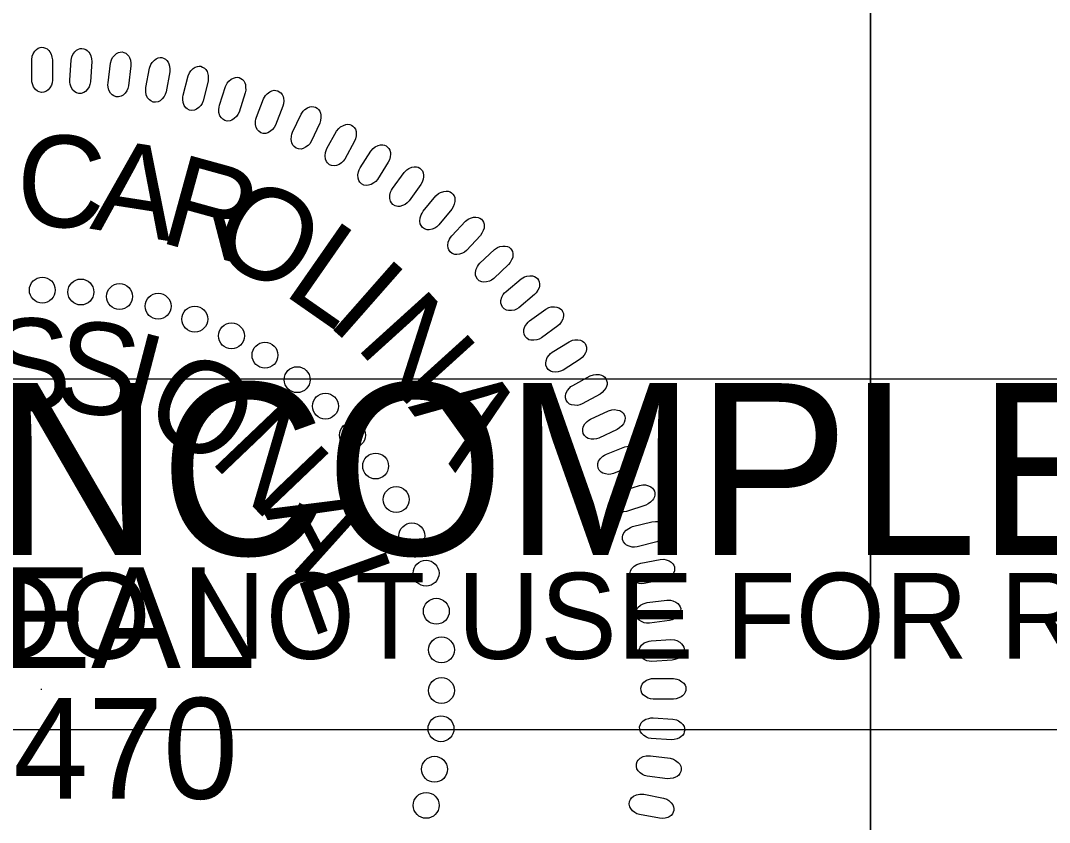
# Model space of a CAD drawing. Extents: x 18938 to 19565, y 6931 to 7973.
# Drawn here: x 19359.81 to 19368.08, y 7502.55 to 7509 of the extents above; entities that cross this region are included whole.
import ezdxf

# ---------------------------------------------------------------- set-up
doc = ezdxf.new("R2010")
doc.units = 0
for name, color, linetype in [('Old_Level_10', 7, 'Continuous'), ('Prop Pavement Schedule Description CELL', 7, 'Continuous'), ('Scratch_Level_5', 7, 'Continuous'), ('Typical Pavement Slope Information CELL', 7, 'Continuous')]:
    doc.layers.add(name, color=color, linetype=linetype)

# ---------------------------------------------------------------- blocks, each defined once
blk = doc.blocks.new('Brandon J. McInnis')
at = {"layer": 'Old_Level_10'}
blk.add_line((-51.239, 50.97), (-51.239, 50.923), dxfattribs=at)
for points in [[(-51.831, 88.656), (-51.831, 89.882), (-51.793, 90.102), (-51.74, 90.242), (-51.628, 90.411), (-51.531, 90.521), (-51.419, 90.601), (-51.315, 90.64), (-51.202, 90.66), (-51.09, 90.64), (-50.97, 90.61), (-50.866, 90.551), (-50.761, 90.451), (-50.701, 90.37), (-50.634, 90.221), (-50.574, 90.042), (-50.552, 89.882), (-50.545, 88.626), (-50.567, 88.456), (-50.613, 88.316), (-50.702, 88.157), (-50.815, 88.017), (-50.912, 87.938), (-51.069, 87.878), (-51.218, 87.858), (-51.367, 87.898), (-51.472, 87.947), (-51.6, 88.047), (-51.719, 88.217), (-51.786, 88.397), (-51.816, 88.526)], [(-49.472, 88.629), (-49.394, 89.854), (-49.344, 90.07), (-49.282, 90.206), (-49.159, 90.368), (-49.056, 90.472), (-48.939, 90.544), (-48.832, 90.577), (-48.718, 90.59), (-48.608, 90.563), (-48.49, 90.526), (-48.39, 90.46), (-48.291, 90.354), (-48.237, 90.27), (-48.179, 90.117), (-48.131, 89.934), (-48.118, 89.773), (-48.191, 88.518), (-48.223, 88.35), (-48.277, 88.214), (-48.377, 88.061), (-48.497, 87.928), (-48.599, 87.854), (-48.76, 87.805), (-48.911, 87.794), (-49.057, 87.843), (-49.158, 87.9), (-49.279, 88.008), (-49.387, 88.184), (-49.443, 88.368), (-49.465, 88.499)], [(-47.109, 88.454), (-46.955, 89.671), (-46.891, 89.884), (-46.821, 90.016), (-46.689, 90.17), (-46.578, 90.267), (-46.457, 90.332), (-46.348, 90.359), (-46.235, 90.364), (-46.126, 90.33), (-46.011, 90.285), (-45.915, 90.213), (-45.823, 90.101), (-45.774, 90.014), (-45.726, 89.857), (-45.69, 89.671), (-45.687, 89.511), (-45.838, 88.263), (-45.881, 88.097), (-45.943, 87.965), (-46.052, 87.818), (-46.181, 87.693), (-46.287, 87.626), (-46.451, 87.587), (-46.601, 87.585), (-46.745, 87.644), (-46.842, 87.706), (-46.956, 87.821), (-47.054, 88.005), (-47.097, 88.191), (-47.111, 88.324)], [(-44.77, 88.168), (-44.54, 89.372), (-44.462, 89.581), (-44.384, 89.708), (-44.242, 89.854), (-44.126, 89.943), (-44.001, 90), (-43.891, 90.02), (-43.777, 90.019), (-43.671, 89.978), (-43.559, 89.926), (-43.467, 89.848), (-43.383, 89.73), (-43.339, 89.641), (-43.301, 89.481), (-43.276, 89.294), (-43.284, 89.132), (-43.513, 87.897), (-43.567, 87.735), (-43.637, 87.606), (-43.755, 87.466), (-43.891, 87.35), (-44.002, 87.29), (-44.167, 87.26), (-44.318, 87.269), (-44.457, 87.336), (-44.55, 87.405), (-44.656, 87.527), (-44.742, 87.716), (-44.775, 87.904), (-44.779, 88.038)], [(-42.465, 87.694), (-42.159, 88.882), (-42.069, 89.085), (-41.983, 89.208), (-41.832, 89.344), (-41.711, 89.426), (-41.582, 89.475), (-41.471, 89.488), (-41.357, 89.479), (-41.254, 89.432), (-41.145, 89.373), (-41.059, 89.289), (-40.983, 89.167), (-40.945, 89.075), (-40.917, 88.913), (-40.903, 88.724), (-40.921, 88.563), (-41.227, 87.345), (-41.291, 87.187), (-41.37, 87.062), (-41.496, 86.93), (-41.639, 86.823), (-41.753, 86.769), (-41.92, 86.751), (-42.07, 86.769), (-42.204, 86.845), (-42.293, 86.919), (-42.392, 87.047), (-42.466, 87.241), (-42.486, 87.432), (-42.483, 87.564)], [(-40.215, 87.072), (-39.835, 88.239), (-39.732, 88.436), (-39.639, 88.552), (-39.48, 88.679), (-39.353, 88.753), (-39.222, 88.794), (-39.11, 88.8), (-38.997, 88.784), (-38.897, 88.73), (-38.793, 88.664), (-38.711, 88.575), (-38.643, 88.449), (-38.611, 88.354), (-38.593, 88.191), (-38.592, 88.002), (-38.619, 87.843), (-39.001, 86.646), (-39.075, 86.491), (-39.161, 86.372), (-39.295, 86.248), (-39.446, 86.151), (-39.562, 86.105), (-39.73, 86.096), (-39.879, 86.124), (-40.008, 86.208), (-40.092, 86.288), (-40.183, 86.422), (-40.244, 86.62), (-40.252, 86.811), (-40.24, 86.944)], [(-37.931, 86.337), (-37.48, 87.477), (-37.364, 87.667), (-37.264, 87.778), (-37.097, 87.895), (-36.966, 87.961), (-36.833, 87.993), (-36.721, 87.992), (-36.609, 87.97), (-36.513, 87.91), (-36.412, 87.838), (-36.337, 87.743), (-36.276, 87.612), (-36.25, 87.516), (-36.242, 87.352), (-36.253, 87.163), (-36.291, 87.007), (-36.747, 85.835), (-36.831, 85.686), (-36.924, 85.573), (-37.066, 85.458), (-37.221, 85.369), (-37.341, 85.331), (-37.509, 85.333), (-37.656, 85.37), (-37.78, 85.462), (-37.859, 85.547), (-37.94, 85.686), (-37.988, 85.888), (-37.985, 86.08), (-37.965, 86.211)], [(-35.69, 85.403), (-35.167, 86.513), (-35.04, 86.695), (-34.933, 86.799), (-34.76, 86.905), (-34.625, 86.963), (-34.49, 86.987), (-34.378, 86.979), (-34.268, 86.949), (-34.175, 86.883), (-34.079, 86.805), (-34.01, 86.706), (-33.958, 86.571), (-33.938, 86.474), (-33.941, 86.309), (-33.963, 86.122), (-34.011, 85.968), (-34.54, 84.828), (-34.632, 84.684), (-34.733, 84.577), (-34.882, 84.471), (-35.043, 84.392), (-35.165, 84.361), (-35.332, 84.374), (-35.476, 84.42), (-35.593, 84.52), (-35.667, 84.609), (-35.74, 84.754), (-35.775, 84.958), (-35.76, 85.149), (-35.732, 85.279)], [(-33.566, 84.388), (-32.975, 85.462), (-32.836, 85.636), (-32.723, 85.734), (-32.543, 85.828), (-32.405, 85.877), (-32.268, 85.893), (-32.158, 85.878), (-32.05, 85.841), (-31.961, 85.77), (-31.871, 85.686), (-31.808, 85.583), (-31.764, 85.445), (-31.75, 85.346), (-31.763, 85.183), (-31.798, 84.997), (-31.854, 84.846), (-32.454, 83.742), (-32.555, 83.604), (-32.662, 83.503), (-32.817, 83.407), (-32.983, 83.338), (-33.107, 83.315), (-33.273, 83.338), (-33.414, 83.393), (-33.526, 83.5), (-33.593, 83.594), (-33.656, 83.743), (-33.679, 83.949), (-33.652, 84.139), (-33.616, 84.267)], [(-31.508, 83.203), (-30.85, 84.238), (-30.701, 84.403), (-30.582, 84.493), (-30.397, 84.576), (-30.256, 84.617), (-30.118, 84.624), (-30.009, 84.602), (-29.903, 84.558), (-29.819, 84.481), (-29.735, 84.392), (-29.678, 84.285), (-29.643, 84.145), (-29.636, 84.046), (-29.659, 83.883), (-29.705, 83.699), (-29.771, 83.553), (-30.439, 82.488), (-30.549, 82.357), (-30.661, 82.264), (-30.823, 82.177), (-30.992, 82.119), (-31.117, 82.103), (-31.282, 82.137), (-31.418, 82.201), (-31.523, 82.314), (-31.585, 82.413), (-31.639, 82.565), (-31.649, 82.772), (-31.609, 82.96), (-31.565, 83.085)], [(-29.508, 81.929), (-28.787, 82.921), (-28.628, 83.078), (-28.503, 83.16), (-28.313, 83.231), (-28.17, 83.262), (-28.032, 83.261), (-27.924, 83.231), (-27.821, 83.182), (-27.742, 83.1), (-27.664, 83.005), (-27.614, 82.896), (-27.588, 82.753), (-27.586, 82.653), (-27.62, 82.493), (-27.677, 82.313), (-27.753, 82.17), (-28.486, 81.149), (-28.604, 81.026), (-28.722, 80.939), (-28.888, 80.862), (-29.061, 80.815), (-29.187, 80.808), (-29.349, 80.852), (-29.481, 80.924), (-29.579, 81.044), (-29.634, 81.146), (-29.679, 81.301), (-29.675, 81.509), (-29.624, 81.694), (-29.572, 81.816)], [(-27.614, 80.513), (-26.831, 81.458), (-26.663, 81.603), (-26.534, 81.678), (-26.339, 81.737), (-26.194, 81.76), (-26.057, 81.749), (-25.951, 81.713), (-25.852, 81.657), (-25.778, 81.571), (-25.705, 81.471), (-25.663, 81.358), (-25.646, 81.215), (-25.65, 81.115), (-25.695, 80.957), (-25.762, 80.78), (-25.846, 80.643), (-26.642, 79.671), (-26.768, 79.554), (-26.892, 79.475), (-27.062, 79.41), (-27.238, 79.373), (-27.364, 79.373), (-27.523, 79.428), (-27.65, 79.508), (-27.74, 79.634), (-27.789, 79.739), (-27.823, 79.897), (-27.807, 80.103), (-27.744, 80.285), (-27.684, 80.404)], [(-25.842, 78.999), (-25.002, 79.893), (-24.825, 80.028), (-24.691, 80.094), (-24.493, 80.14), (-24.347, 80.154), (-24.211, 80.135), (-24.107, 80.093), (-24.011, 80.03), (-23.944, 79.939), (-23.877, 79.835), (-23.841, 79.72), (-23.834, 79.576), (-23.845, 79.476), (-23.898, 79.321), (-23.977, 79.15), (-24.07, 79.018), (-24.926, 78.097), (-25.058, 77.989), (-25.186, 77.918), (-25.361, 77.864), (-25.538, 77.838), (-25.664, 77.847), (-25.819, 77.91), (-25.942, 77.998), (-26.023, 78.13), (-26.065, 78.238), (-26.09, 78.397), (-26.061, 78.603), (-25.987, 78.779), (-25.92, 78.894)], [(-24.098, 77.306), (-23.203, 78.145), (-23.018, 78.268), (-22.88, 78.326), (-22.68, 78.36), (-22.533, 78.364), (-22.399, 78.337), (-22.297, 78.288), (-22.206, 78.22), (-22.144, 78.124), (-22.084, 78.017), (-22.056, 77.899), (-22.057, 77.755), (-22.075, 77.657), (-22.138, 77.505), (-22.227, 77.339), (-22.328, 77.213), (-23.24, 76.348), (-23.379, 76.248), (-23.511, 76.185), (-23.689, 76.142), (-23.867, 76.128), (-23.992, 76.144), (-24.143, 76.218), (-24.26, 76.313), (-24.334, 76.449), (-24.369, 76.56), (-24.383, 76.721), (-24.341, 76.924), (-24.256, 77.096), (-24.182, 77.206)], [(-22.486, 75.559), (-21.54, 76.341), (-21.347, 76.452), (-21.206, 76.501), (-21.004, 76.522), (-20.857, 76.517), (-20.725, 76.482), (-20.627, 76.426), (-20.54, 76.353), (-20.484, 76.254), (-20.431, 76.142), (-20.41, 76.023), (-20.421, 75.879), (-20.444, 75.782), (-20.517, 75.635), (-20.617, 75.475), (-20.726, 75.356), (-21.69, 74.55), (-21.834, 74.459), (-21.971, 74.404), (-22.151, 74.372), (-22.33, 74.369), (-22.453, 74.393), (-22.6, 74.476), (-22.71, 74.579), (-22.774, 74.719), (-22.803, 74.832), (-22.807, 74.993), (-22.752, 75.193), (-22.657, 75.36), (-22.576, 75.465)], [(-21.026, 73.737), (-20.033, 74.458), (-19.833, 74.556), (-19.69, 74.596), (-19.486, 74.605), (-19.341, 74.591), (-19.21, 74.547), (-19.116, 74.486), (-19.034, 74.407), (-18.984, 74.304), (-18.939, 74.19), (-18.925, 74.07), (-18.945, 73.927), (-18.974, 73.831), (-19.056, 73.689), (-19.166, 73.535), (-19.281, 73.423), (-20.294, 72.679), (-20.444, 72.598), (-20.584, 72.552), (-20.765, 72.531), (-20.945, 72.54), (-21.066, 72.571), (-21.207, 72.663), (-21.311, 72.772), (-21.366, 72.917), (-21.387, 73.03), (-21.382, 73.192), (-21.315, 73.388), (-21.209, 73.548), (-21.121, 73.649)], [(-19.625, 71.791), (-18.589, 72.448), (-18.383, 72.534), (-18.238, 72.565), (-18.035, 72.561), (-17.889, 72.538), (-17.762, 72.486), (-17.672, 72.418), (-17.596, 72.335), (-17.552, 72.229), (-17.514, 72.112), (-17.508, 71.992), (-17.537, 71.85), (-17.572, 71.757), (-17.662, 71.619), (-17.782, 71.473), (-17.904, 71.369), (-18.961, 70.689), (-19.116, 70.618), (-19.259, 70.581), (-19.441, 70.571), (-19.619, 70.591), (-19.739, 70.63), (-19.874, 70.731), (-19.97, 70.846), (-20.017, 70.994), (-20.031, 71.109), (-20.014, 71.27), (-19.936, 71.461), (-19.82, 71.615), (-19.726, 71.709)], [(-18.364, 69.741), (-17.289, 70.332), (-17.078, 70.404), (-16.931, 70.426), (-16.728, 70.41), (-16.585, 70.377), (-16.461, 70.317), (-16.376, 70.244), (-16.305, 70.156), (-16.268, 70.048), (-16.237, 69.929), (-16.238, 69.809), (-16.276, 69.669), (-16.317, 69.578), (-16.416, 69.447), (-16.544, 69.308), (-16.673, 69.211), (-17.771, 68.6), (-17.931, 68.538), (-18.075, 68.51), (-18.257, 68.512), (-18.433, 68.543), (-18.551, 68.589), (-18.679, 68.698), (-18.768, 68.82), (-18.805, 68.97), (-18.812, 69.086), (-18.786, 69.245), (-18.694, 69.432), (-18.569, 69.577), (-18.47, 69.666)], [(-17.256, 67.658), (-16.146, 68.18), (-15.932, 68.239), (-15.784, 68.252), (-15.582, 68.222), (-15.442, 68.181), (-15.321, 68.113), (-15.241, 68.036), (-15.175, 67.943), (-15.146, 67.833), (-15.122, 67.712), (-15.131, 67.592), (-15.177, 67.455), (-15.224, 67.367), (-15.331, 67.241), (-15.468, 67.112), (-15.603, 67.023), (-16.737, 66.482), (-16.9, 66.431), (-17.045, 66.411), (-17.227, 66.425), (-17.402, 66.467), (-17.515, 66.52), (-17.636, 66.637), (-17.718, 66.764), (-17.745, 66.916), (-17.744, 67.032), (-17.709, 67.19), (-17.606, 67.37), (-17.472, 67.508), (-17.367, 67.589)], [(-16.277, 65.497), (-15.136, 65.948), (-14.919, 65.994), (-14.77, 65.997), (-14.571, 65.955), (-14.433, 65.905), (-14.318, 65.83), (-14.242, 65.747), (-14.182, 65.65), (-14.16, 65.538), (-14.143, 65.416), (-14.16, 65.298), (-14.215, 65.163), (-14.267, 65.078), (-14.381, 64.96), (-14.526, 64.839), (-14.666, 64.76), (-15.832, 64.29), (-15.998, 64.249), (-16.144, 64.239), (-16.326, 64.264), (-16.496, 64.317), (-16.607, 64.378), (-16.72, 64.502), (-16.793, 64.634), (-16.811, 64.787), (-16.803, 64.903), (-16.758, 65.058), (-16.644, 65.231), (-16.502, 65.36), (-16.392, 65.435)], [(-15.403, 63.183), (-14.236, 63.561), (-14.016, 63.593), (-13.867, 63.587), (-13.671, 63.533), (-13.536, 63.474), (-13.426, 63.392), (-13.356, 63.305), (-13.302, 63.204), (-13.287, 63.092), (-13.278, 62.969), (-13.303, 62.851), (-13.366, 62.72), (-13.422, 62.639), (-13.545, 62.528), (-13.696, 62.416), (-13.841, 62.345), (-15.034, 61.95), (-15.202, 61.92), (-15.349, 61.92), (-15.528, 61.955), (-15.696, 62.018), (-15.802, 62.087), (-15.908, 62.217), (-15.972, 62.353), (-15.98, 62.508), (-15.965, 62.623), (-15.91, 62.775), (-15.786, 62.94), (-15.636, 63.06), (-15.522, 63.129)], [(-14.658, 61.01), (-13.47, 61.314), (-13.249, 61.332), (-13.1, 61.317), (-12.907, 61.25), (-12.777, 61.184), (-12.672, 61.094), (-12.608, 61.003), (-12.56, 60.899), (-12.552, 60.786), (-12.551, 60.662), (-12.583, 60.547), (-12.654, 60.42), (-12.716, 60.342), (-12.844, 60.24), (-13.004, 60.137), (-13.152, 60.076), (-14.368, 59.757), (-14.537, 59.737), (-14.684, 59.745), (-14.861, 59.792), (-15.024, 59.866), (-15.125, 59.941), (-15.222, 60.078), (-15.279, 60.218), (-15.277, 60.372), (-15.255, 60.486), (-15.19, 60.634), (-15.056, 60.792), (-14.898, 60.902), (-14.78, 60.963)], [(-14.148, 58.755), (-12.944, 58.985), (-12.721, 58.989), (-12.574, 58.964), (-12.386, 58.885), (-12.261, 58.811), (-12.16, 58.715), (-12.102, 58.62), (-12.062, 58.514), (-12.061, 58.4), (-12.068, 58.276), (-12.107, 58.163), (-12.185, 58.041), (-12.252, 57.967), (-12.387, 57.873), (-12.552, 57.781), (-12.704, 57.729), (-13.938, 57.487), (-14.108, 57.477), (-14.253, 57.495), (-14.427, 57.554), (-14.585, 57.638), (-14.682, 57.718), (-14.77, 57.861), (-14.817, 58.005), (-14.806, 58.158), (-14.777, 58.27), (-14.703, 58.414), (-14.559, 58.563), (-14.394, 58.663), (-14.273, 58.716)], [(-13.75, 56.316), (-12.533, 56.469), (-12.311, 56.46), (-12.166, 56.426), (-11.983, 56.335), (-11.862, 56.253), (-11.769, 56.152), (-11.716, 56.053), (-11.683, 55.944), (-11.689, 55.83), (-11.703, 55.708), (-11.749, 55.596), (-11.836, 55.48), (-11.907, 55.411), (-12.048, 55.325), (-12.218, 55.243), (-12.373, 55.201), (-13.619, 55.037), (-13.79, 55.038), (-13.935, 55.065), (-14.104, 55.134), (-14.256, 55.228), (-14.348, 55.314), (-14.427, 55.462), (-14.465, 55.609), (-14.444, 55.762), (-14.408, 55.872), (-14.325, 56.01), (-14.172, 56.15), (-14.002, 56.239), (-13.877, 56.285)], [(-13.507, 53.952), (-12.282, 54.028), (-12.061, 54.004), (-11.919, 53.961), (-11.742, 53.86), (-11.627, 53.77), (-11.54, 53.662), (-11.494, 53.561), (-11.467, 53.45), (-11.48, 53.337), (-11.502, 53.215), (-11.555, 53.107), (-11.648, 52.997), (-11.724, 52.932), (-11.869, 52.855), (-12.045, 52.784), (-12.202, 52.752), (-13.457, 52.666), (-13.627, 52.678), (-13.769, 52.715), (-13.934, 52.794), (-14.08, 52.897), (-14.166, 52.989), (-14.236, 53.142), (-14.265, 53.29), (-14.234, 53.441), (-14.191, 53.549), (-14.099, 53.682), (-13.938, 53.812), (-13.763, 53.891), (-13.635, 53.928)], [(-13.358, 51.621), (-12.131, 51.621), (-11.912, 51.583), (-11.772, 51.531), (-11.602, 51.419), (-11.492, 51.322), (-11.413, 51.209), (-11.373, 51.105), (-11.354, 50.992), (-11.373, 50.88), (-11.403, 50.761), (-11.463, 50.656), (-11.563, 50.552), (-11.643, 50.492), (-11.792, 50.424), (-11.972, 50.365), (-12.131, 50.342), (-13.388, 50.335), (-13.557, 50.358), (-13.697, 50.403), (-13.857, 50.493), (-13.996, 50.604), (-14.076, 50.702), (-14.136, 50.859), (-14.156, 51.008), (-14.115, 51.158), (-14.066, 51.262), (-13.966, 51.39), (-13.796, 51.509), (-13.617, 51.576), (-13.487, 51.606)], [(-13.391, 49.18), (-12.166, 49.103), (-11.951, 49.052), (-11.814, 48.991), (-11.651, 48.868), (-11.548, 48.764), (-11.476, 48.648), (-11.443, 48.541), (-11.43, 48.427), (-11.457, 48.317), (-11.494, 48.199), (-11.56, 48.099), (-11.667, 48.001), (-11.75, 47.946), (-11.904, 47.888), (-12.087, 47.84), (-12.248, 47.827), (-13.502, 47.899), (-13.669, 47.932), (-13.806, 47.987), (-13.96, 48.085), (-14.091, 48.206), (-14.166, 48.308), (-14.215, 48.469), (-14.226, 48.62), (-14.176, 48.766), (-14.12, 48.867), (-14.013, 48.988), (-13.836, 49.096), (-13.652, 49.152), (-13.522, 49.174)], [(-13.558, 46.841), (-12.34, 46.686), (-12.127, 46.622), (-11.995, 46.553), (-11.84, 46.42), (-11.744, 46.31), (-11.68, 46.189), (-11.653, 46.08), (-11.648, 45.966), (-11.681, 45.857), (-11.726, 45.742), (-11.798, 45.646), (-11.91, 45.555), (-11.997, 45.506), (-12.154, 45.457), (-12.339, 45.421), (-12.501, 45.419), (-13.748, 45.569), (-13.914, 45.613), (-14.047, 45.675), (-14.193, 45.784), (-14.318, 45.912), (-14.385, 46.019), (-14.424, 46.182), (-14.425, 46.333), (-14.367, 46.476), (-14.305, 46.574), (-14.19, 46.688), (-14.007, 46.784), (-13.82, 46.829), (-13.688, 46.842)], [(-13.954, 44.454), (-12.75, 44.223), (-12.541, 44.145), (-12.413, 44.069), (-12.268, 43.926), (-12.178, 43.81), (-12.121, 43.685), (-12.102, 43.574), (-12.103, 43.46), (-12.143, 43.354), (-12.196, 43.242), (-12.274, 43.151), (-12.392, 43.067), (-12.481, 43.023), (-12.641, 42.985), (-12.828, 42.96), (-12.989, 42.968), (-14.225, 43.196), (-14.387, 43.25), (-14.516, 43.321), (-14.655, 43.439), (-14.772, 43.575), (-14.832, 43.685), (-14.861, 43.851), (-14.853, 44.002), (-14.785, 44.141), (-14.717, 44.234), (-14.595, 44.34), (-14.406, 44.426), (-14.217, 44.458), (-14.084, 44.463)]]:
    blk.add_lwpolyline(points, close=True, dxfattribs=at)
for centre in [(-51.174, 75.639), (-48.785, 75.519), (-46.397, 75.239), (-44.008, 74.641), (-41.739, 73.843), (-39.47, 72.807), (-37.4, 71.611), (-35.41, 70.097), (-33.659, 68.463), (-31.987, 66.669), (-30.554, 64.757), (-29.281, 62.685), (-28.309, 60.436), (-27.434, 58.125), (-26.797, 55.774), (-26.48, 53.384), (-26.48, 50.874), (-26.51, 48.51), (-26.909, 46.001), (-27.427, 43.77)]:
    blk.add_circle(centre, 0.801, dxfattribs=at)
for s, height, rotation, p in [('C', 5.669, 357.58768, (-52.856, 79.65)), ('A', 5.669, 351.09832, (-48.281, 79.442)), ('R', 5.669, 344.60896, (-44.074, 78.648)), ('O', 5.669, 331.63025, (-41.119, 77.994)), ('L', 5.669, 325.14089, (-36.386, 75.463)), ('I', 5.669, 318.65154, (-33.693, 73.61)), ('N', 5.669, 312.16218, (-31.888, 72.189)), ('S', 5.669, 1.28903, (-54.398, 68.157)), ('S', 5.669, 353.34923, (-50.537, 68.259)), ('I', 5.669, 345.40944, (-46.736, 67.627)), ('O', 5.669, 329.52984, (-45.233, 67.455)), ('A', 5.669, 305.67282, (-28.568, 68.409)), ('N', 5.669, 313.65025, (-40.921, 65.151)), ('A', 5.669, 297.77065, (-37.584, 62.07)), ('L', 5.669, 289.83086, (-35.46, 58.076)), ('SEAL', 6.2363, 359.98136, (-59.282, 52.264)), ('29470', 6.2363, 359.98136, (-62.253, 44.185))]:
    blk.add_text(s, height=height, rotation=rotation, dxfattribs=at).set_placement(p)

msp = doc.modelspace()

# ---------------------------------------------------------------- linework, layer by layer
at = {"layer": 'Scratch_Level_5'}
msp.add_lwpolyline([(19358.0043, 7503.2984), (19358.0043, 7506.1184), (19375.6443, 7506.1184), (19375.6443, 7503.2984)], close=True, dxfattribs=at)
at = {"layer": 'Typical Pavement Slope Information CELL'}
msp.add_line((19366.642, 7512.0513), (19366.642, 7497.0135), dxfattribs=at)
for points in [[(19353.1353, 7512.0513), (19366.642, 7512.0513), (19366.642, 7497.0068), (19353.1353, 7497.0068)], [(19366.642, 7512.0513), (19380.142, 7512.0513), (19380.142, 7497.0068), (19366.642, 7497.0068)]]:
    msp.add_lwpolyline(points, close=True, dxfattribs=at)

# ---------------------------------------------------------------- block references
at = {"layer": 'Prop Pavement Schedule Description CELL', "xscale": 0.13, "yscale": 0.13}
msp.add_blockref('Brandon J. McInnis', (19366.6353, 7497.0001), dxfattribs=at)

# ---------------------------------------------------------------- texts
at = {"layer": 'Scratch_Level_5'}
for s, height, p in [('INCOMPLETE PLANS', 1.3824, (19359.0783, 7504.7024)), ('DO NOT USE FOR R/W ACQUISITION', 0.6912, (19359.4683, 7503.8684))]:
    msp.add_text(s, height=height, dxfattribs=at).set_placement(p)

doc.saveas('drawing.dxf')
